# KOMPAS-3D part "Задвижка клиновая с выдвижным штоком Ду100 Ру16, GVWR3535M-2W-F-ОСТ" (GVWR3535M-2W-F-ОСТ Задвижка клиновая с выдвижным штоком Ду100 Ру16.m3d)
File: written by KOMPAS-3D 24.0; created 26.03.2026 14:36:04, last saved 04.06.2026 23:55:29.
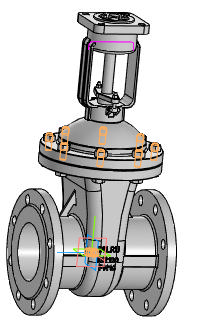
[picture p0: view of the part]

Document properties: Автор: R2D2; Полное имя файла: E:\Работа\Зайцев\GVWR3535M-2W-F-ОСТ Задвижка клиновая 30нж941нж DN.ru Ду50-200 Ру16\исходные данные\DN100\GVWR3535M-2W-F-ОСТ Задвижка клиновая с выдвижным штоком Ду100 Ру16.m3d

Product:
- Component [detail]: ANSI B18.2.4.2M - M5x0,8 - 8  | designation ANSI B18.2.4.2M - M5x0,8  | qty 2  | pos. 2  | Комментарий: Типы метрических   шестигранных гаек   2; Автор: R2D2; additional columns: Сталь, мягкая; source file: ANSI B18.2.4.2M - M5x0,8 ANSI B18.2.4.2M - M5x0,8 - 8.m3d
- Component [detail]: Деталь1  | qty 1  | pos. 3  | additional columns: Типовые; source file: 2.m3d
- Component [detail]: Фланец  | qty 2  | pos. 3  | Автор: R2D2; additional columns: Типовые; source file: Фланец DN100 PN16 b20.m3d
- Component [standard]: Болт М12-6gx50.88.45Г.019 ГОСТ 7798-70  | qty 8  | Материал: Сталь 45Г (density 7850 kg/m3); Масса: 0.06053; Раздел спецификации: Стандартные изделия; Рассекать на разрезах: no; additional columns: BOSimple***Material:39848d99-529e-4aa2-825c-393daa009d15
- Component [standard]: Гайка М12-6H ГОСТ 5915-70  | qty 24  | Масса: 0.0184; Раздел спецификации: Стандартные изделия; Рассекать на разрезах: no
- Component [assembly]: DN50_3D_STEP  | designation Сборка  | qty 1  | pos. 4  | Масса: 2.725126; Автор: R2D2; source file: Фланец А.a3d
- Body: Тело 1  | qty 1
    Масса: 48.906112
- Part/product: Задвижка клиновая с выдвижным штоком Ду100 Ру16  | designation GVWR3535M-2W-F-ОСТ
    Масса: 25.5
    Раздел спецификации: Прочие изделия
    Примечание: D040-10557

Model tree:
1. Массив по концентрической сетке:1  (labels: Грань.Твердое тело1)  (8 pattern instances)
     Шаг 2 = 360
2. Массив по концентрической сетке:2  (labels: Грань.Твердое тело1)  (2 pattern instances)
     Шаг 2 = 360
3. Элемент выдавливания:1  (with: Грань.Элемент выдавливания:2, Грань.Элемент вращения:1)
     Расстояние 1 = 15.5338
4. Элемент выдавливания:2  (with: Грань.Элемент выдавливания:1, Грань.Элемент вращения:1)
     Расстояние 1 = 9.79311
5. Элемент выдавливания:3  (with: Грань.Элемент выдавливания:1)
     Расстояние 1 = 20
6. Эскиз:1  (with: Вершина.Элемент выдавливания:3, Ребро.Элемент выдавливания:3)
7. Элемент по траектории:1  (with: Грань.Элемент выдавливания:3)
     Толщина стенки 1 = 1; Длина траектории = 107.708
8. Скругление:1  (with: Ребро.Элемент выдавливания:1, Ребро.Элемент выдавливания:2)
     Радиус = 3
9. Элемент выдавливания:4  (with: Грань.Элемент выдавливания:1, Грань.Элемент по траектории:1)
     Расстояние 1 = 81.7998
10. Эскиз:2
11. Элемент выдавливания:5  (with: Грань.Элемент выдавливания:1, Грань.Элемент вращения:1, Грань.Операция без истории:2)  (labels: Грань.Твердое тело1; Грань.Solid1; Solid1; Твердое тело1)
     Расстояние 1 = 76; Смещение 1 = 1; Расстояние = -115; Ориентация = 2; Расстояние = -415

Referenced files in E:\Работа\Зайцев\GVWR3535M-2W-F-ОСТ Задвижка клиновая 30нж941нж DN.ru Ду50-200 Ру16\исходные данные\DN100\: ANSI B18.2.4.2M - M5x0,8 ANSI B18.2.4.2M - M5x0,8 - 8.m3d, 2.m3d, Фланец DN100 PN16 b20.m3d, Фланец А.a3d
Referenced files in C:\Program Files\ASCON\KOMPAS-3D v24\Libs\PolynomLib\DATA\vault\Methods\Kompas\3D\: PLib_Bolt_1_900.m3d, PLib_Nut_OST92_900.m3d
Referenced files in E:\Работа\Зайцев\GVWR2626M-2W-F-S Задвижка клиновая с выдвижным штоком DN.ru Ду50-300 Ру16\DN100\исходные материалы\: Фланец DN100 PN16 b20.m3d
Referenced files in E:\Работа\Зайцев\GVWR3131M-2W-F-S Задвижка клиновая с выдвижным штоком DN.ru Ду50-200 Ру63\DN100\исходные материалы\: ANSI B18.2.4.2M - M5x0,8 ANSI B18.2.4.2M - M5x0,8 - 8.m3d
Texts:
  BOSimple***PART:25ccc031-f2ed-a43b-e633-090566d53ffa***SHORTLOC:Root±30±20±10±80±10±©{}30±©{BASE}130±290[9;Цинковое, хроматированное;Сталь 45Г ГОСТ 4543-2016;50;12;19;1,75;8.8]
  BOSimple***Material:39848d99-529e-4aa2-825c-393daa009d15
  BOSimple***PART:dfaf85ed-3e43-003f-b29c-9c5b054070d3***SHORTLOC:Root±30±10±20±©{}110±10±50±60[Нет;Без покрытия;Без указания материала;-;12;1,75;19]
  GVWR3535M-2W-F-ОСТ
  DN100
  GOST 26.020 Pr3
  PN16
  ANSI B18.2.4.2M - M5x0,8 ANSI B18.2.4.2M - M5x0,8 - 8 (1)
  Деталь1 Деталь1
  Фланец (1)
  Фланец (2)
  Болт М12-6gx50.88.45Г.019 ГОСТ 7798-70 (1)
  hole1
  hole2
  Гайка М12-6H ГОСТ 5915-70 (1)
  bcut1
  hcut1
  cut1
  Гайка М12-6H ГОСТ 5915-70 (2)
  Гайка М12-6H ГОСТ 5915-70 (3)
  Гайка М12-6H ГОСТ 5915-70 (4)
  Гайка М12-6H ГОСТ 5915-70 (5)
  Гайка М12-6H ГОСТ 5915-70 (6)
  Болт М12-6gx50.88.45Г.019 ГОСТ 7798-70 (2)
  Гайка М12-6H ГОСТ 5915-70 (7)
  Гайка М12-6H ГОСТ 5915-70 (8)
  Гайка М12-6H ГОСТ 5915-70 (9)
  Болт М12-6gx50.88.45Г.019 ГОСТ 7798-70 (3)
  Гайка М12-6H ГОСТ 5915-70 (10)
  Гайка М12-6H ГОСТ 5915-70 (11)
  Гайка М12-6H ГОСТ 5915-70 (12)
  Болт М12-6gx50.88.45Г.019 ГОСТ 7798-70 (4)
  Гайка М12-6H ГОСТ 5915-70 (13)
  Гайка М12-6H ГОСТ 5915-70 (14)
  Гайка М12-6H ГОСТ 5915-70 (15)
  Болт М12-6gx50.88.45Г.019 ГОСТ 7798-70 (5)
  Гайка М12-6H ГОСТ 5915-70 (16)
  Гайка М12-6H ГОСТ 5915-70 (17)
  Гайка М12-6H ГОСТ 5915-70 (18)
  Болт М12-6gx50.88.45Г.019 ГОСТ 7798-70 (6)
  Гайка М12-6H ГОСТ 5915-70 (19)
  Гайка М12-6H ГОСТ 5915-70 (20)
  Гайка М12-6H ГОСТ 5915-70 (21)
  Болт М12-6gx50.88.45Г.019 ГОСТ 7798-70 (7)
  Гайка М12-6H ГОСТ 5915-70 (22)
  Гайка М12-6H ГОСТ 5915-70 (23)
  Гайка М12-6H ГОСТ 5915-70 (24)
  Болт М12-6gx50.88.45Г.019 ГОСТ 7798-70 (8)
  ANSI B18.2.4.2M - M5x0,8 ANSI B18.2.4.2M - M5x0,8 - 8 (2)
  Сборка DN50_3D_STEP
  Ось Z.Начало координат
  Ось Y.Начало координат
  Плоскость ZX.Начало координат
  Плоскость XY.Начало координат
  Plane. Начало координат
